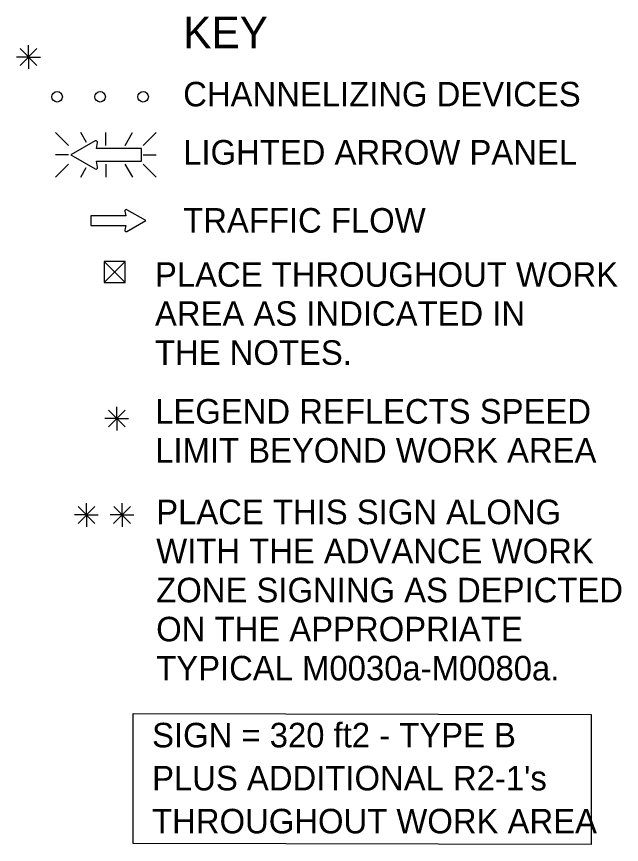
# Model space of a CAD drawing. Extents: x 16726 to 18482, y 5650 to 7013.
# Drawn here: x 17195.9 to 17425.1, y 6607.5 to 6921.3 of the extents above; entities that cross this region are included whole.
import ezdxf

# ---------------------------------------------------------------- set-up
doc = ezdxf.new("R2010")
doc.units = 0
for name, color, linetype in [('MT_SCRATCH_LEVEL_E', 7, 'Continuous'), ('TRAFFIC_SIGNS_PR', 7, 'Continuous'), ('TYPICAL_TEXT_DIMEN_EX', 7, 'Continuous'), ('TYPICAL_TEXT_DIMEN_PR', 7, 'Continuous')]:
    doc.layers.add(name, color=color, linetype=linetype)

msp = doc.modelspace()

# ---------------------------------------------------------------- linework, layer by layer
at = {"layer": 'MT_SCRATCH_LEVEL_E'}
for p, q in [((17236.96, 6847.63), (17237.27, 6845.86)), ((17244.88, 6844.01), (17237.64, 6848.12)), ((17237.27, 6845.86), (17224.01, 6845.86)), ((17224.01, 6845.86), (17224.01, 6842.11)), ((17237.64, 6839.86), (17244.88, 6844.01)), ((17224.01, 6842.11), (17237.27, 6842.11)), ((17237.27, 6842.11), (17236.96, 6840.34))]:
    msp.add_line(p, q, dxfattribs=at)
for centre, start, end in [((17237.41, 6847.71), 60.4248, 189.9638), ((17237.42, 6840.27), 170.0362, 299.7731)]:
    msp.add_arc(centre, 0.463, start, end, dxfattribs=at)
at = {"layer": 'TRAFFIC_SIGNS_PR'}
for p, q in [((17210.69, 6877.39), (17215.62, 6872.46)), ((17222.45, 6873.57), (17220.25, 6877.39)), ((17229.77, 6872.46), (17229.77, 6877.39)), ((17237.01, 6872.46), (17239.86, 6877.39)), ((17243.92, 6872.46), (17248.86, 6877.39)), ((17215.62, 6868.9), (17210.69, 6868.9)), ((17243.92, 6868.9), (17248.86, 6868.9)), ((17210.69, 6860.41), (17215.62, 6865.34)), ((17220.2, 6860.41), (17222.32, 6864.07)), ((17229.77, 6865.34), (17229.77, 6860.41)), ((17239.9, 6860.41), (17237.05, 6865.34)), ((17243.92, 6865.34), (17248.86, 6860.41))]:
    msp.add_line(p, q, dxfattribs=at)
for points in [[(17225.7, 6874.18), (17216.41, 6868.9), (17225.7, 6863.58)], [(17226.58, 6864.21), (17226.18, 6866.47), (17243.19, 6866.47), (17243.19, 6871.28), (17226.18, 6871.28), (17226.58, 6873.56)]]:
    msp.add_lwpolyline(points, dxfattribs=at)
for centre in [(17211.26, 6890.93), (17227.56, 6890.93), (17243.86, 6890.93)]:
    msp.add_circle(centre, 2, dxfattribs=at)
for centre, radius, start, end in [((17225.99, 6873.65), 0.598, 350.7308, 118.8916), ((17225.99, 6864.1), 0.597, 241.4833, 9.9593)]:
    msp.add_arc(centre, radius, start, end, dxfattribs=at)
at = {"layer": 'TYPICAL_TEXT_DIMEN_EX'}
msp.add_lwpolyline([(17240.03, 6657.12), (17413.7, 6656.74), (17413.7, 6607.55), (17240.03, 6607.93)], close=True, dxfattribs=at)
at = {"layer": 'TYPICAL_TEXT_DIMEN_PR'}
for p, q in [((17200.43, 6906), (17200.43, 6910.45)), ((17197.24, 6909.19), (17203.62, 6902.81)), ((17203.62, 6909.19), (17197.24, 6902.81)), ((17200.43, 6906), (17195.9, 6906)), ((17200.43, 6906), (17203.62, 6906)), ((17200.43, 6906), (17204.91, 6906)), ((17200.43, 6906), (17200.43, 6901.5)), ((17229.05, 6828.52), (17237.05, 6820.52)), ((17229.05, 6820.52), (17237.05, 6828.52)), ((17237.07, 6772.15), (17230.69, 6765.77)), ((17230.7, 6772.15), (17237.07, 6765.77)), ((17233.88, 6768.96), (17233.88, 6773.41)), ((17233.88, 6768.96), (17229.35, 6768.96)), ((17233.88, 6768.96), (17237.07, 6768.96)), ((17233.88, 6768.96), (17238.36, 6768.96)), ((17233.88, 6768.96), (17233.88, 6764.46)), ((17219.19, 6735.61), (17225.56, 6729.24)), ((17225.56, 6735.61), (17219.19, 6729.24)), ((17222.38, 6732.43), (17222.38, 6736.88)), ((17239.07, 6735.61), (17232.69, 6729.24)), ((17232.7, 6735.61), (17239.07, 6729.24)), ((17235.88, 6732.43), (17235.88, 6736.88)), ((17222.38, 6732.43), (17217.84, 6732.43)), ((17222.38, 6732.43), (17225.56, 6732.43)), ((17222.38, 6732.43), (17226.85, 6732.43)), ((17222.38, 6732.43), (17222.38, 6727.93)), ((17235.88, 6732.43), (17231.35, 6732.43)), ((17235.88, 6732.43), (17239.07, 6732.43)), ((17235.88, 6732.43), (17240.36, 6732.43)), ((17235.88, 6732.43), (17235.88, 6727.93))]:
    msp.add_line(p, q, dxfattribs=at)
msp.add_lwpolyline([(17229.05, 6828.52), (17229.05, 6820.52), (17237.05, 6820.52), (17237.05, 6828.52)], close=True, dxfattribs=at)
for points in [[(17267.72, 6885.65), (17267.73, 6885.65), (17267.74, 6885.65), (17267.74, 6885.65)], [(17326.83, 6769.54), (17326.85, 6769.54), (17326.86, 6769.54), (17326.86, 6769.54)]]:
    msp.add_open_spline(points, degree=2, dxfattribs=at)

# ---------------------------------------------------------------- texts
at = {"layer": 'TRAFFIC_SIGNS_PR'}
for s, p in [('PLACE THIS SIGN ALONG', (17248.82, 6728.93)), ('WITH THE ADVANCE WORK', (17248.82, 6714.13)), ('ZONE SIGNING AS DEPICTED', (17248.82, 6699.33)), ('ON THE APPROPRIATE', (17248.82, 6684.53)), ('TYPICAL M0030a-M0080a.', (17248.82, 6669.73))]:
    msp.add_text(s, height=9.3, dxfattribs=at).set_placement(p)
at = {"layer": 'TYPICAL_TEXT_DIMEN_EX'}
for s, height, p in [('KEY', 12, (17259.05, 6909.34)), ('CHANNELIZING DEVICES', 9.3, (17259.05, 6887.29)), ('LIGHTED ARROW PANEL', 9.3, (17259.05, 6865.24)), ('TRAFFIC FLOW', 9.3, (17259.05, 6839.44)), ('PLACE THROUGHOUT WORK', 9.3, (17248.35, 6818.93)), ('AREA AS INDICATED IN', 9.3, (17248.35, 6804.13)), ('THE NOTES.', 9.3, (17248.35, 6789.33)), ('LEGEND REFLECTS SPEED', 9.3, (17248.43, 6767.06)), ('LIMIT BEYOND WORK AREA', 9.3, (17248.43, 6752.26)), ('SIGN = 320 ft2 - TYPE B', 9.3, (17247.26, 6644.34)), ("PLUS ADDITIONAL R2-1's", 9.3, (17247.26, 6628.04)), ('THROUGHOUT WORK AREA', 9.3, (17247.26, 6611.74))]:
    msp.add_text(s, height=height, dxfattribs=at).set_placement(p)

doc.saveas('drawing.dxf')
